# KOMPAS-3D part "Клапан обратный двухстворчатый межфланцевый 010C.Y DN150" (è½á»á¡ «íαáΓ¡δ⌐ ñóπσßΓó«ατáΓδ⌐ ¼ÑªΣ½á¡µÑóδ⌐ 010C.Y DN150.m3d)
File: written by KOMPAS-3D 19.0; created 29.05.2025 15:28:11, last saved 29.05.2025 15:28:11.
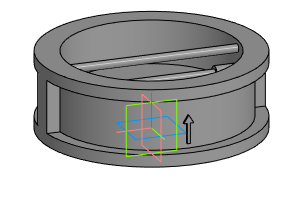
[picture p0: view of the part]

Document properties: Полное имя файла: E:\Dendor Работа Сачек\3D для проекитирвщиков\5.2 Тип 010C, 010C.Y Клапан обратный двухстворчатый межфланцевый\stp_Клапан обратный двухстворчатый межфланцевый 010C.Y\Клапан обратный двухстворчатый межфланцевый 010C.Y DN150.m3d

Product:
- Part/product: Клапан обратный двухстворчатый межфланцевый 010C.Y DN150

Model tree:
1. Операция без истории:1  (labels: Клапан обратный двухстворчатый межфланцевый 010C.Y DN150)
